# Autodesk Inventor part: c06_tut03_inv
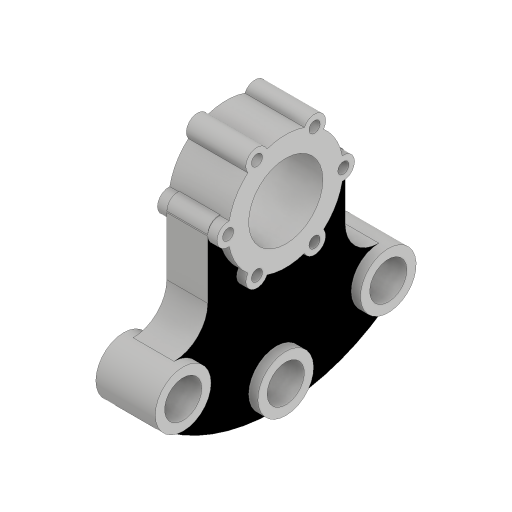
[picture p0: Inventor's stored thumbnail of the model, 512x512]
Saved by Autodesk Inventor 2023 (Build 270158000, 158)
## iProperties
Created: 2015-03
Part Number: c06_tut03_inv
Material: Generic
Document SubType Name: Modeling
Designer: Sandeep
Density: 1 g/cm^3
Appearance: Default
Author: Sandeep
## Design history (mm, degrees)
sketch "Sketch1"
  geometry: L1 (-37, -31.635)-(-37, 0.365); L2 (0, 14.952)-(0, -99.335); L3 (37, 0.365)-(37, -31.635); L4 (-55.203, -64.635)-(-64.945, -76.041); L5 (55.203, -64.635)-(64.945, -76.041); L6 (0, 0)-(41.78, 0); A1 r 31 centre (0, 0) between (30.347, 6.33) and (-30.347, 6.33); A2 r 18 centre (-55, -31.635) between (-55.111, -49.635) and (-37, -31.635); A3 r 15 centre (-55.203, -64.635) between (-55.111, -49.635) and (-64.945, -76.041); A4 r 100 centre (0, 0) between (-64.945, -76.041) and (64.945, -76.041); A5 r 18 centre (55, -31.635) between (37, -31.635) and (55.111, -49.635); A6 r 15 centre (55.203, -64.635) between (64.945, -76.041) and (55.111, -49.635); A7 r 6 centre (-31, 0.365) between (-30.347, 6.33) and (-37, 0.365); A8 r 6 centre (31, 0.365) between (37, 0.365) and (30.347, 6.33); 1 further point
  constraints: 16 point on circle, 12 end point, 8 centre point, 7 tangent, 3 vertical, 2 coincident, 2 symmetric about line, 1 horizontal, 1 parallel, 1 point on line, 3 other
  dimensions: "d0" = 31 radius of A1; "d2" = 18 radius of A5; "d3" = 15 radius of A6; "d4" = 100 radius of A4; "d6" = 81 deg angle of L5 L4; "d7" = 65 vertical distance of L3.start L5.start; "d8" = 6 radius of A7; "d10" = 74 distance between parallel lines of L3 L1
extrude "Extrusion1" new body sketch "Sketch1" stored distance "d11" = 22; taper "d12" = 0 deg
sketch "Sketch5"
  geometry: L1 (0, 48.219)-(0, -124.115); L2 (0, 0)-(43.472, 0); L3 (0, 0)-(17.524, 30.352); A1 r 6 centre (31.011, 0) between (30.42, -5.971) and (30.42, 5.971); A2 r 31 centre (0, 0) between (30.347, 6.33) and (-30.347, 6.33) reference; A3 r 6 centre (15.5, 26.847) between (20.381, 23.358) and (10.038, 29.33); A4 r 31 centre (0, 0) between (30.42, 5.971) and (20.381, 23.358); A5 r 6 centre (-31.011, 0) between (-30.42, 5.971) and (-30.42, -5.971); A6 r 6 centre (-15.5, 26.847) between (-10.038, 29.33) and (-20.381, 23.358); A7 r 6 centre (-15.5, -26.847) between (-20.381, -23.358) and (-10.038, -29.33); A8 r 6 centre (15.5, -26.847) between (10.038, -29.33) and (20.381, -23.358); A9 r 31 centre (0, 0) between (10.038, 29.33) and (-10.038, 29.33); A10 r 31 centre (0, 0) between (-20.381, 23.358) and (-30.42, 5.971); A11 r 31 centre (0, 0) between (-30.42, -5.971) and (-20.381, -23.358); A12 r 31 centre (0, 0) between (-10.038, -29.33) and (10.038, -29.33); A13 r 31 centre (0, 0) between (20.381, -23.358) and (30.42, -5.971); 2 further points
  constraints: 28 point on circle, 12 centre point, 12 symmetric about line, 6 end point, 3 point on line, 1 coincident, 1 horizontal, 1 vertical, 4 other
  dimensions: "d19" = 12 diameter of A1; "d20" = 60 deg angle of L2 L3; "d21" = 12 diameter of A3
extrude "Extrusion2" join sketch "Sketch5" stored distance "d22" = 32; taper "d23" = 0 deg
hole "Hole1" diameter "d26" = 6; stored, may be unused: countersink angle "d30" = 90 deg, drill point angle "d32" = 118 deg; dims "d24" = 10, "d25" = 10, "d27" = 6, "d28" = 4, "d29" = 2, "d31" = 8
pattern_circular "Circular Pattern1" dims angle "d34" = 360 deg
sketch "Sketch6"
  geometry: A1 r 15 centre (-55.203, -64.635) between (-55.111, -49.635) and (-64.945, -76.041) reference; 2 further points
  constraints: 1 coincident, 3 other
extrude "Extrusion3" join sketch "Sketch6" stored distance "d36" = 32; taper "d37" = 0 deg
hole "Hole2" diameter "d40" = 20; stored, may be unused: countersink angle "d44" = 90 deg, drill point angle "d46" = 118 deg; dims "d41" = 6, "d42" = 4, "d43" = 2, "d45" = 8, "d59" = 10, "d60" = 10
pattern_circular "Circular Pattern2" dims angle "d48" = 81 deg
hole "Hole3" diameter "d52" = 40; stored, may be unused: countersink angle "d56" = 90 deg, drill point angle "d58" = 118 deg; dims "d50" = 10, "d51" = 10, "d53" = 6, "d54" = 4, "d55" = 2, "d57" = 8
body "Solid1"
other parameters: "d18" = 62
